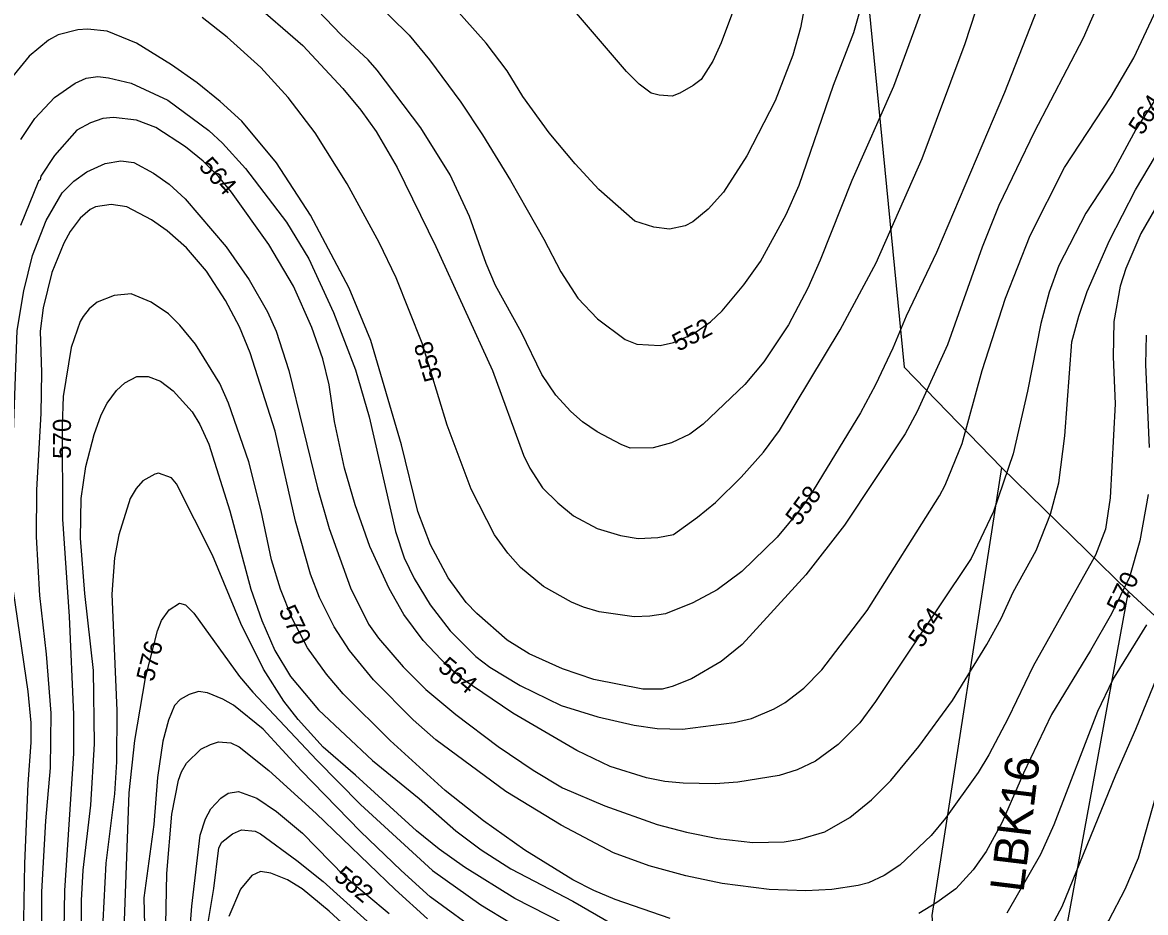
# Model space of a CAD drawing. Extents: x -709418 to -703832, y -1161719 to -1157826.
# Drawn here: x -709148.5 to -708650.5, y -1159940.7 to -1159546.1 of the extents above; entities that cross this region are included whole.
import ezdxf

# ---------------------------------------------------------------- set-up
doc = ezdxf.new("R2010")
doc.units = 0
for name, color, linetype in [('120_vrstevnice hlavní', 7, 'Continuous'), ('121_vrstevnice hlavní_popis', 7, 'Continuous'), ('122_vrstevnice základní', 7, 'Continuous'), ('609_LBC_stav', 7, 'Continuous'), ('611_LBK_stav', 7, 'Continuous'), ('612_LBK_stav_popis', 7, 'Continuous')]:
    doc.layers.add(name, color=color, linetype=linetype)

msp = doc.modelspace()

# ---------------------------------------------------------------- linework, layer by layer
at = {"layer": '120_vrstevnice hlavní'}
for points in [[(-708668.08, -1159530), (-708678.21, -1159553.14), (-708699.91, -1159594.8), (-708715.53, -1159627.2), (-708722.9, -1159645.71), (-708738.38, -1159689.1), (-708751.83, -1159718.61), (-708757.04, -1159728.45), (-708783.94, -1159768.95), (-708801.16, -1159790.93), (-708829.36, -1159821.89), (-708838.76, -1159829.41), (-708851.78, -1159837.07), (-708860.46, -1159840.55), (-708864.8, -1159841.7), (-708873.48, -1159841.7), (-708895.18, -1159837.36), (-708909.06, -1159832.59), (-708923.82, -1159826.08), (-708933.65, -1159820.01), (-708947.1, -1159808.15), (-708951.73, -1159803.23), (-708959.69, -1159792.38), (-708967.64, -1159777.63), (-708973.14, -1159762.87), (-708980.37, -1159733.36), (-708993.97, -1159687.08), (-709003.66, -1159663.94), (-709020.73, -1159631.54), (-709035.92, -1159608.39)], [(-708800, -1159529.71), (-708803.47, -1159548.51), (-708806.94, -1159560.66), (-708814.75, -1159580.91), (-708827.34, -1159605.21), (-708837.61, -1159621.41), (-708844.41, -1159628.93), (-708851.2, -1159634.57), (-708854.68, -1159636.31), (-708861.62, -1159637.76), (-708868.56, -1159636.89), (-708876.95, -1159634.14), (-708893.01, -1159620.11), (-708903.42, -1159608.83), (-708914.99, -1159595.08), (-708926.71, -1159578.89), (-708933.65, -1159567.6), (-708942.91, -1159555.31), (-708967.35, -1159527.82)], [(-709035.92, -1159608.39), (-709051.25, -1159589.88), (-709060.79, -1159581.2), (-709071.06, -1159572.96), (-709082.49, -1159564.85), (-709097.97, -1159555.31), (-709110.98, -1159549.96), (-709119.66, -1159549.09), (-709124, -1159549.38), (-709132.68, -1159551.55), (-709137.02, -1159554.01), (-709145.56, -1159561.09), (-709156.84, -1159574.83)], [(-709013.64, -1159835.05), (-709022.17, -1159823.33), (-709028.97, -1159810.32), (-709034.03, -1159797.3), (-709038.08, -1159784.28), (-709042.71, -1159762.58), (-709048.07, -1159740.89), (-709057.18, -1159714.85), (-709060.94, -1159706.17), (-709071.79, -1159688.81), (-709078.73, -1159680.28), (-709083.79, -1159675.36), (-709091.46, -1159670.16), (-709100.28, -1159666.4), (-709107.8, -1159667.12), (-709115.32, -1159670.16), (-709118.94, -1159673.05), (-709121.54, -1159676.52), (-709122.99, -1159678.69), (-709126.9, -1159690.26), (-709130.51, -1159711.96), (-709130.95, -1159724.98), (-709130.8, -1159766.34), (-709127.76, -1159809.45), (-709125.88, -1159852.84), (-709125.88, -1159870.2), (-709129.93, -1159930.95), (-709130.51, -1159965.66)], [(-708650.29, -1159684.77), (-708650.58, -1159697.78), (-708648.85, -1159734.52)], [(-708649.28, -1159755.35), (-708653.04, -1159775.89), (-708657.67, -1159792.09), (-708665.62, -1159808.29), (-708674.88, -1159824.49), (-708692.24, -1159852.84), (-708704.68, -1159878.88), (-708714.08, -1159900.57), (-708721.17, -1159913.59), (-708726.95, -1159921.84), (-708734.62, -1159930.23), (-708743.01, -1159936.3), (-708751.11, -1159941.07)], [(-708861.33, -1159943.39), (-708885.63, -1159934.85), (-708895.18, -1159930.95), (-708904.43, -1159926.18), (-708925.7, -1159913.01), (-708944.07, -1159900), (-708961.13, -1159886.54), (-708985.43, -1159864.41), (-709006.26, -1159843.73), (-709013.64, -1159835.05)], [(-709085.09, -1159953.51), (-709084.52, -1159923.43), (-709082.35, -1159897.1), (-709079.31, -1159882.06), (-709078.01, -1159878.3), (-709075.84, -1159874.54), (-709069.47, -1159868.32), (-709065.13, -1159866.15), (-709061.66, -1159865.08), (-709056.17, -1159865.43), (-709052.39, -1159867.22)], [(-709052.39, -1159867.22), (-709039.24, -1159877.72), (-709018.33, -1159896.84), (-708983.26, -1159930.52), (-708968.94, -1159943.53)]]:
    msp.add_lwpolyline(points, dxfattribs=at)
at = {"layer": '122_vrstevnice základní'}
for points in [[(-709059.78, -1159599.57), (-709049.66, -1159610.85), (-709031.43, -1159634.72), (-709021.59, -1159650.92), (-709010.6, -1159674.64), (-709000.91, -1159700.1), (-708994.84, -1159720.93), (-708983.12, -1159771.84), (-708979.21, -1159783.41), (-708974.88, -1159792.67), (-708967.79, -1159804.24), (-708958.82, -1159815.81), (-708947.54, -1159827.24), (-708941.32, -1159831.87), (-708927.86, -1159840.11), (-708909.64, -1159848.94), (-708893.44, -1159854), (-708877.24, -1159857.61), (-708867.11, -1159859.06), (-708855.83, -1159859.35), (-708832.98, -1159856.46), (-708825.17, -1159854.72), (-708815.19, -1159850.38), (-708810.27, -1159847.63), (-708802.02, -1159841.27), (-708794.07, -1159833.17), (-708773.96, -1159806.84), (-708741.85, -1159755.93), (-708739.39, -1159751.3), (-708731.87, -1159732.79), (-708722.9, -1159700.39), (-708712.63, -1159668.28), (-708701.64, -1159640.5), (-708686.45, -1159610.42), (-708665.77, -1159578.89), (-708655.64, -1159561.82), (-708636.84, -1159521.32)], [(-709047.34, -1159536.07), (-709024.2, -1159556.32), (-709006.41, -1159575.41), (-708998.45, -1159584.96), (-708991.65, -1159594.51), (-708982.4, -1159610.42), (-708965.18, -1159645.42), (-708940.16, -1159700.39), (-708926.27, -1159737.99), (-708923.53, -1159743.78), (-708917.89, -1159752.46), (-708911.09, -1159759.11), (-708904.14, -1159764.9), (-708893.73, -1159770.39), (-708883.32, -1159773.58), (-708875.5, -1159774.88), (-708866.83, -1159774.44), (-708859.88, -1159773.14), (-708849.18, -1159765.48), (-708841.22, -1159758.97), (-708829.8, -1159747.69), (-708819.96, -1159736.55), (-708812.87, -1159727), (-708785.97, -1159682.45), (-708769.91, -1159652.65), (-708749.52, -1159606.37), (-708730.43, -1159555.45), (-708721.17, -1159526.81)], [(-708993.68, -1159535.2), (-708977.04, -1159551.69), (-708968.08, -1159562.69), (-708954.19, -1159581.49), (-708944.5, -1159595.95), (-708932.06, -1159616.2), (-708917.31, -1159642.24), (-708909.79, -1159656.7), (-708902.26, -1159668.28), (-708893.58, -1159677.53), (-708881.29, -1159686.65), (-708876.08, -1159688.81), (-708865.67, -1159689.39), (-708859.88, -1159687.95), (-708851.2, -1159684.33), (-708843.39, -1159678.83), (-708838.19, -1159673.92), (-708828.64, -1159662.49), (-708821.26, -1159652.07), (-708809.84, -1159631.25), (-708804.05, -1159618.23), (-708788.86, -1159573.97), (-708779.89, -1159550.54), (-708772.52, -1159524.5)], [(-708829.65, -1159530.86), (-708838.76, -1159555.16), (-708842.38, -1159563.26), (-708847.59, -1159571.36), (-708851.06, -1159574.11), (-708856.99, -1159577.44), (-708860.46, -1159578.74), (-708866.25, -1159578.31), (-708869.72, -1159577.44), (-708875.07, -1159573.53), (-708880.71, -1159567.89), (-708903.71, -1159540.99)], [(-708748.65, -1159537.52), (-708762.25, -1159574.55), (-708780.76, -1159616.2), (-708794.79, -1159651.5), (-708800.29, -1159663.94), (-708808.82, -1159680.14), (-708819.82, -1159696.63), (-708828.21, -1159706.61), (-708846.72, -1159724.25), (-708852.65, -1159728.59), (-708860.75, -1159732.5), (-708868.85, -1159734.67), (-708878.98, -1159734.81), (-708883.03, -1159733.22), (-708893.73, -1159727.58), (-708900.24, -1159723.1), (-708905.3, -1159718.61), (-708911.95, -1159711.38), (-708918.17, -1159702.12), (-708927.29, -1159683.61), (-708938.71, -1159662.78), (-708942.91, -1159652.94), (-708950.29, -1159632.11), (-708958.82, -1159613.6), (-708971.84, -1159592.77), (-708991.22, -1159567.31), (-708995.27, -1159562.69), (-709007.13, -1159551.55), (-709021.16, -1159537.08)], [(-708698.75, -1159540.7), (-708713.07, -1159577.15), (-708743.15, -1159648.03), (-708756.61, -1159676.38), (-708762.54, -1159690.55), (-708770.2, -1159706.75), (-708776.86, -1159719.19), (-708799.57, -1159756.22), (-708803.76, -1159762.15), (-708813.89, -1159774.3), (-708829.51, -1159789.49), (-708840.5, -1159797.59), (-708851.2, -1159803.37), (-708863.35, -1159808.29), (-708870.3, -1159809.3), (-708877.24, -1159809.59), (-708892.86, -1159807.42), (-708899.8, -1159805.4), (-708905.01, -1159803.08), (-708917.45, -1159796.14), (-708927.72, -1159787.75), (-708933.36, -1159781.39), (-708939.15, -1159773.29), (-708949.56, -1159753.04), (-708960.12, -1159724.69), (-708971.26, -1159688.24), (-708982.83, -1159659.31), (-708990.35, -1159643.69), (-709004.53, -1159617.65), (-709018.7, -1159595.08), (-709030.71, -1159579.46)], [(-709030.71, -1159579.46), (-709042.86, -1159566.16), (-709057.76, -1159552.7), (-709068.89, -1159543.88)], [(-708635.54, -1159563.84), (-708654.78, -1159593.64), (-708664.9, -1159612.15), (-708677.05, -1159630.67), (-708688.91, -1159653.81), (-708693.25, -1159665.67), (-708697.01, -1159679.56), (-708702.8, -1159709.64), (-708709.16, -1159737.42), (-708717.99, -1159762.87), (-708727.82, -1159783.7), (-708770.2, -1159847.2), (-708777.15, -1159856.6), (-708786.84, -1159866.15), (-708796.82, -1159873.53), (-708804.92, -1159877.43), (-708813.02, -1159879.89), (-708831.24, -1159882.93), (-708841.37, -1159883.65), (-708855.54, -1159883.36), (-708863.64, -1159882.64), (-708871.74, -1159881.05), (-708887.94, -1159875.99), (-708902.7, -1159868.9), (-708931.05, -1159852.26), (-708953.47, -1159837.07), (-708960.12, -1159831.29), (-708970.82, -1159820.15), (-708979.36, -1159808.58), (-708985.87, -1159797.01), (-708994.55, -1159778.5), (-709001.06, -1159759.98), (-709005.68, -1159743.78), (-709010.17, -1159722.95), (-709012.48, -1159706.75), (-709015.38, -1159695.18), (-709020.15, -1159681.29)], [(-709149.17, -1159597.98), (-709143.1, -1159588.72), (-709134.27, -1159579.46), (-709125.16, -1159573.1), (-709120.24, -1159570.79), (-709115.04, -1159570.06), (-709110.41, -1159570.64), (-709100.28, -1159573.1), (-709084.08, -1159580.62), (-709065.86, -1159594.07), (-709059.78, -1159599.57)], [(-709020.15, -1159681.29), (-709028.39, -1159663.07), (-709039.24, -1159644.55), (-709055.88, -1159621.41), (-709061.52, -1159614.47), (-709068.32, -1159607.67), (-709076.27, -1159601.31), (-709089.43, -1159592.63), (-709097.97, -1159589.44), (-709108.09, -1159588.29), (-709112.86, -1159588.72), (-709118.41, -1159590.68), (-709124.46, -1159593.86), (-709134.29, -1159605.11), (-709140.35, -1159614.32), (-709140.64, -1159615.91), (-709141.36, -1159616.49), (-709149.32, -1159636.16)], [(-709090.45, -1159612.88), (-709083.5, -1159617.8), (-709076.42, -1159624.3), (-709058.19, -1159645.57), (-709047.92, -1159660.18), (-709039.82, -1159674.35), (-709036.06, -1159683.03), (-709030.42, -1159700.39), (-709017.69, -1159752.46), (-709012.48, -1159770.39), (-709003.08, -1159796.72), (-708995.12, -1159812.92), (-708990.64, -1159819), (-708979.65, -1159831.72), (-708969.67, -1159841.85), (-708956.36, -1159852.84), (-708937.56, -1159867.16), (-708922.08, -1159877.58), (-708909.06, -1159885.39), (-708890.26, -1159893.34), (-708867.11, -1159901.73), (-708854.1, -1159905.06), (-708840.21, -1159907.81), (-708824.59, -1159909.69), (-708810.7, -1159909.4), (-708803.76, -1159908.24), (-708792.77, -1159904.91), (-708781.63, -1159898.55), (-708772.05, -1159890.72), (-708763.48, -1159882.16), (-708750.97, -1159867.02), (-708736.07, -1159846.77), (-708720.88, -1159821.89), (-708714.52, -1159810.32), (-708709.16, -1159798.75), (-708699.04, -1159780.23), (-708692.67, -1159764.03), (-708688.91, -1159750.14), (-708686.31, -1159729.31), (-708683.13, -1159687.66), (-708680.09, -1159676.38), (-708676.33, -1159665.38), (-708666.49, -1159642.82), (-708654.92, -1159620.25), (-708640.46, -1159595.95)], [(-709148.01, -1159952.07), (-709147.44, -1159918.94), (-709145.99, -1159883.65), (-709144.69, -1159865.28), (-709144.69, -1159856.6), (-709145.99, -1159842.72), (-709152.5, -1159798.17), (-709155.1, -1159769.24), (-709154.67, -1159756.8), (-709152.64, -1159731.92), (-709150.91, -1159682.74), (-709147.87, -1159665.09), (-709144.11, -1159649.47), (-709138.03, -1159633.85), (-709130.95, -1159621.7), (-709125.74, -1159616.49), (-709119.95, -1159612.3), (-709111.85, -1159608.68), (-709104.91, -1159607.52), (-709099.12, -1159608.25), (-709090.45, -1159612.88)], [(-709020.73, -1159790.65), (-709027.38, -1159767.21), (-709036.49, -1159727.29), (-709047.49, -1159692.58), (-709052.26, -1159681), (-709058.48, -1159669.43), (-709066.87, -1159656.42), (-709075.84, -1159646), (-709084.37, -1159638.48), (-709091.31, -1159633.56), (-709102.31, -1159627.92), (-709109.25, -1159626.76), (-709116.19, -1159627.92), (-709118.51, -1159629.08), (-709122.99, -1159632.84), (-709127.33, -1159638.77), (-709130.22, -1159643.98), (-709135.43, -1159656.99), (-709139.34, -1159672.61), (-709140.64, -1159683.03), (-709140.06, -1159701.25), (-709140.35, -1159719.48), (-709142.23, -1159753.33), (-709142.37, -1159774.16), (-709140.93, -1159800.19), (-709138.03, -1159826.23), (-709136.01, -1159852.26), (-709136.3, -1159876.56), (-709138.32, -1159900), (-709140.06, -1159931.53), (-709139.91, -1159962.48)], [(-708646.53, -1159629.22), (-708652.61, -1159639.64), (-708659.26, -1159655.26), (-708661.72, -1159663.07), (-708664.61, -1159678.69), (-708664.9, -1159694.31), (-708664.03, -1159715.14), (-708666.2, -1159756.8), (-708668.23, -1159770.68), (-708672.71, -1159782.26), (-708700.34, -1159831.43), (-708711.48, -1159854.58), (-708720.01, -1159870.78), (-708724.78, -1159878.59), (-708739.25, -1159898.84), (-708745.61, -1159906.51), (-708759.5, -1159919.67), (-708766.44, -1159924.3), (-708773.39, -1159927.48), (-708778.01, -1159928.78), (-708789.59, -1159930.52), (-708801.16, -1159931.09), (-708817.36, -1159930.52), (-708838.19, -1159927.77), (-708854.39, -1159924.44), (-708870.59, -1159919.96), (-708886.5, -1159914.17), (-708909.64, -1159902.02), (-708934.23, -1159886.98), (-708965.18, -1159864.12), (-708975.31, -1159855.3), (-708992.81, -1159837.51), (-709003.51, -1159824.49), (-709010.31, -1159814.08), (-709016.82, -1159801.06), (-709020.73, -1159790.65)], [(-709122.56, -1159956.12), (-709122.41, -1159935.29), (-709121.54, -1159921.98), (-709118.22, -1159893.05), (-709116.63, -1159865.86), (-709117.06, -1159833.46), (-709120.82, -1159799.32), (-709122.85, -1159774.73), (-709122.56, -1159757.09), (-709120.39, -1159742.91), (-709116.77, -1159728.74), (-709113.59, -1159720.06), (-709110.98, -1159714.85), (-709106.79, -1159709.35), (-709103.17, -1159705.88), (-709097.82, -1159703.13), (-709092.76, -1159703.14), (-709087.26, -1159705.16), (-709081.62, -1159709.5), (-709073.23, -1159718.76), (-709069.91, -1159724.4), (-709065.86, -1159733.08), (-709056.6, -1159762.58), (-709047.2, -1159797.3), (-709042.42, -1159811.18), (-709036.64, -1159824.49), (-709029.7, -1159836.06), (-709017.26, -1159850.82), (-708993.24, -1159873.24), (-708972.56, -1159890.16), (-708956.36, -1159904.48), (-708945.08, -1159912.87), (-708931.92, -1159921.26), (-708904.43, -1159935.72), (-708874.06, -1159953.23)], [(-708973.86, -1159904.48), (-709000.91, -1159879.75), (-709015.23, -1159867.45), (-709026.22, -1159855.16), (-709032.59, -1159847.06), (-709041.7, -1159832.88), (-709051.68, -1159812.63), (-709064.27, -1159782.26), (-709080.18, -1159750.72), (-709082.49, -1159747.97), (-709088.13, -1159745.95), (-709089.87, -1159746.38), (-709095.07, -1159749.28), (-709098.11, -1159752.75), (-709100.72, -1159757.09), (-709105.78, -1159773.29), (-709107.66, -1159783.41), (-709108.96, -1159799.61), (-709106.65, -1159851.11), (-709106.79, -1159873.96), (-709107.66, -1159888.14), (-709111.56, -1159918.8), (-709112.86, -1159944.55)], [(-709103.46, -1159948.31), (-709101.15, -1159887.56), (-709098.69, -1159864.41), (-709093.92, -1159836.64), (-709088.71, -1159815.81), (-709086.83, -1159811.18), (-709083.5, -1159806.56), (-709078.87, -1159803.52), (-709076.27, -1159804.24), (-709072.51, -1159808), (-709052.26, -1159836.06), (-709046.33, -1159843.01), (-709017.98, -1159873.09), (-708998.6, -1159892.76), (-708966.63, -1159922.13), (-708945.22, -1159937.31), (-708918.9, -1159953.23)], [(-708711.91, -1159940.79), (-708697.01, -1159914.75), (-708691.08, -1159901.73), (-708671.7, -1159851.4), (-708665.05, -1159837.51), (-708650, -1159813.21)], [(-708643.93, -1159832.3), (-708654.92, -1159859.5), (-708663.89, -1159879.75), (-708687.61, -1159938.18), (-708697.45, -1159956.41), (-708705.11, -1159967.11), (-708708.73, -1159971.31), (-708721.31, -1159981.14), (-708740.98, -1159992.42), (-708758.05, -1159998.64), (-708782.35, -1160003.13), (-708791.03, -1160003.85), (-708799.71, -1160002.69), (-708811.86, -1159998.79), (-708822.28, -1159994.01), (-708839.63, -1159983.02), (-708869.43, -1159967.83), (-708901.25, -1159949.32), (-708930.18, -1159934.42), (-708952.46, -1159920.54), (-708963.74, -1159912.58), (-708973.86, -1159904.48)], [(-708944.21, -1159950.91), (-708967.79, -1159933.7), (-708980.66, -1159922.13), (-708998.6, -1159904.77), (-709024.92, -1159877.72), (-709041.85, -1159859.35), (-709055.01, -1159848.79), (-709059.64, -1159846.04), (-709066.44, -1159843.3), (-709070.48, -1159842.72), (-709074.54, -1159844.02), (-709078.59, -1159846.33), (-709081.04, -1159848.94), (-709083.79, -1159855.45), (-709086.25, -1159864.7), (-709088.71, -1159880.9), (-709090.3, -1159901.73), (-709094.64, -1159934.13), (-709093.92, -1159964.51)], [(-708817.65, -1160014.12), (-708807.52, -1160019.76), (-708797.4, -1160022.8), (-708793.35, -1160022.94), (-708780.91, -1160021.21), (-708744.17, -1160010.36), (-708731.44, -1160005.73), (-708724.06, -1160001.82), (-708707.14, -1159990.69), (-708701.06, -1159985.77), (-708687.47, -1159972.61), (-708678.79, -1159963.35), (-708666.78, -1159944.26), (-708659.55, -1159930.37), (-708653.62, -1159916.49), (-708638, -1159860.94)], [(-709075.26, -1159961.18), (-709073.38, -1159937.89), (-709069.76, -1159906.36), (-709067.3, -1159899.13), (-709064.99, -1159894.79), (-709060.5, -1159890.02), (-709057.23, -1159887.81), (-709052.69, -1159887.08), (-709044.62, -1159890.02), (-709035.8, -1159895.89)], [(-709035.8, -1159895.89), (-709024.34, -1159905.49), (-709005.65, -1159924.59), (-708985.87, -1159941.07)], [(-709066.29, -1159945.99), (-709063.69, -1159930.08), (-709061.37, -1159912), (-709060.07, -1159909.54), (-709055.44, -1159905.78), (-709051.39, -1159904.05), (-709045.32, -1159904.62), (-709043, -1159905.78), (-709026.8, -1159917.64), (-709015.23, -1159926.9), (-708991.08, -1159948.6)], [(-709038.37, -1159923.28), (-709043, -1159922.56), (-709046.84, -1159924.31), (-709051.83, -1159930.37), (-709057.03, -1159942.52)], [(-708974.15, -1159975.36), (-709012.48, -1159940.06), (-709024.49, -1159930.23), (-709031, -1159926.18), (-709038.37, -1159923.28)]]:
    msp.add_lwpolyline(points, dxfattribs=at)
at = {"layer": '609_LBC_stav'}
msp.add_lwpolyline([(-708714.45, -1159743.35), (-708658.04, -1159798.39), (-708548.12, -1159900.08), (-708538.67, -1159887.93), (-708476.53, -1159570.63), (-708469.78, -1159508.53), (-708476.53, -1159454.52), (-708467.08, -1159418.06), (-708467.08, -1159395.11), (-708560.28, -1159416.71), (-708625.12, -1159419.42), (-708727.77, -1159459.92), (-708773.68, -1159459.8), (-708776.69, -1159502.72), (-708757.49, -1159698.9), (-708714.45, -1159743.35)], dxfattribs=at)
at = {"layer": '611_LBK_stav'}
for points in [[(-708714.45, -1159743.35), (-708745.34, -1159942.03), (-708724.47, -1160207.43)], [(-708659.51, -1160225.11), (-708684.9, -1159944.72), (-708658.04, -1159798.39)]]:
    msp.add_lwpolyline(points, dxfattribs=at)

# ---------------------------------------------------------------- texts
at = {"layer": '121_vrstevnice hlavní_popis'}
for s, rotation, p in [('564', 57.099, (-708651.98, -1159596.49)), ('564', 312.4523, (-709070.74, -1159610.24)), ('552', 27.5172, (-708857.73, -1159692.18)), ('558', 106.8421, (-708962.3, -1159703.89)), ('570', 89.8506, (-709127.05, -1159739.6)), ('558', 54.0683, (-708804.35, -1159769.74)), ('570', 63.9655, (-708661, -1159808.28)), ('570', 296.1217, (-709035.11, -1159806.84)), ('564', 56.1795, (-708749.67, -1159823.8)), ('576', 76.1654, (-709090.43, -1159838.69)), ('564', 320.1438, (-708964.79, -1159832.82)), ('582', 319.9914, (-709010.87, -1159925.45))]:
    msp.add_text(s, height=8, rotation=rotation, dxfattribs=at).set_placement(p)
at = {"layer": '612_LBK_stav_popis'}
msp.add_text('LBK16', height=15, rotation=83.0528, dxfattribs=at).set_placement((-708704.64, -1159932.1))

doc.saveas('drawing.dxf')
